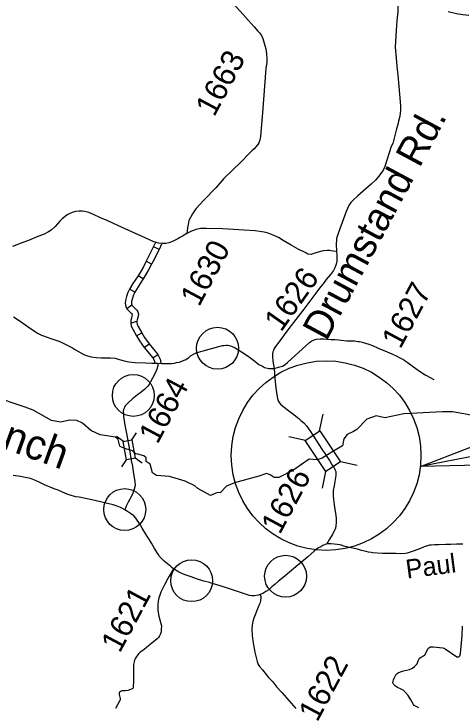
# Model space of a CAD drawing. Extents: x 1376167 to 1379209, y 761324 to 763997.
# Drawn here: x 1376443.7 to 1376526.6, y 762704.2 to 762832.7 of the extents above; entities that cross this region are included whole.
import ezdxf

# ---------------------------------------------------------------- set-up
doc = ezdxf.new("R2010")
doc.units = 0
for name, color, linetype in [('Default', 7, 'Continuous'), ('Old_Level_1', 7, 'Continuous'), ('Prop DSN Text', 7, 'Continuous')]:
    doc.layers.add(name, color=color, linetype=linetype)

msp = doc.modelspace()

# ---------------------------------------------------------------- linework, layer by layer
at = {"layer": 'Default'}
for p, q in [((1376469.55, 762789.54), (1376470.58, 762789.09)), ((1376469.16, 762786.31), (1376468.16, 762786.83)), ((1376467.61, 762783.56), (1376466.65, 762784.15)), ((1376466.05, 762781.14), (1376465.07, 762781.69)), ((1376465.51, 762778.68), (1376464.56, 762778.04)), ((1376465.31, 762775.34), (1376466.43, 762775.71)), ((1376466.35, 762773.02), (1376467.33, 762773.57)), ((1376467.8, 762770.85), (1376468.69, 762771.54)), ((1376469.38, 762768.95), (1376470.33, 762769.57)), ((1376582.4, 762761.32), (1376518.9, 762748.79)), ((1376500.26, 762755.39), (1376500.89, 762758.49)), ((1376463.93, 762753.47), (1376462.64, 762754.37)), ((1376465.49, 762753.75), (1376466.39, 762755.04)), ((1376497.63, 762753.65), (1376494.53, 762754.29)), ((1376463.63, 762748.77), (1376464.53, 762750.07)), ((1376467.41, 762749.45), (1376466.12, 762750.35)), ((1376507.21, 762749.02), (1376504.12, 762749.65)), ((1376500.79, 762744.78), (1376501.42, 762747.87))]:
    msp.add_line(p, q, dxfattribs=at)
for points in [[(1376514.5, 762837.69), (1376514.66, 762835.92), (1376514.73, 762833.03), (1376514.55, 762831.4), (1376514.4, 762829.63), (1376514.26, 762826.49), (1376514.63, 762822.34)], [(1376483.67, 762835.3), (1376486.09, 762832.57), (1376487.01, 762831.53), (1376488.15, 762830.27), (1376488.85, 762829.45), (1376489.15, 762829.14), (1376489.49, 762828.68), (1376489.74, 762828.14), (1376490.13, 762826.84), (1376490.29, 762826.21), (1376490.43, 762825.25), (1376490.51, 762824.42), (1376490.47, 762823.69), (1376490.37, 762823), (1376490.32, 762822.58), (1376489.66, 762814.31), (1376489.29, 762810.01), (1376489.19, 762809.29), (1376489.01, 762808.81), (1376488.83, 762808.48), (1376488.12, 762807.68), (1376487.73, 762807.31), (1376487.42, 762806.98), (1376485.67, 762805.22), (1376482.51, 762802.18), (1376481.04, 762800.47), (1376478.82, 762798.18), (1376477.37, 762796.57), (1376476.71, 762795.62), (1376476.07, 762794.41), (1376475.9, 762793.63), (1376475.79, 762793.04), (1376475.67, 762791.98)], [(1376524.07, 762833.11), (1376525.61, 762832.77), (1376526.77, 762832.56), (1376527.9, 762832.44)], [(1376514.63, 762822.34), (1376514.75, 762821.36), (1376515.22, 762815.63), (1376515.22, 762814.91), (1376515.16, 762814.18), (1376515.05, 762813.46), (1376514.87, 762812.82), (1376514.72, 762812.17), (1376514.47, 762811.36), (1376513.78, 762808.67), (1376513.51, 762808.07), (1376512.33, 762804.41), (1376512.06, 762803.82), (1376511.76, 762803.34), (1376511.14, 762802.52), (1376510.58, 762801.89), (1376509.77, 762801.1), (1376507.33, 762798.95), (1376506.38, 762798.12), (1376506.03, 762797.73), (1376505.66, 762797.19), (1376505.15, 762796.07), (1376504.67, 762794.72), (1376503.73, 762792.18), (1376503.41, 762791.07), (1376503.35, 762790.8), (1376503.3, 762790.03), (1376503.39, 762788.66)], [(1376470.44, 762790.22), (1376469.59, 762790.46), (1376467.3, 762791.5), (1376466.29, 762791.93), (1376462.88, 762793.47), (1376461.08, 762794.3), (1376459.68, 762794.88), (1376458.39, 762795.5), (1376457.53, 762795.85), (1376456.82, 762796.04), (1376456.29, 762796.13), (1376455.77, 762796.11), (1376455.04, 762796.06), (1376454.47, 762795.86), (1376453.91, 762795.62), (1376453.51, 762795.42), (1376453.13, 762795.13), (1376452.63, 762794.71), (1376452.14, 762794.24), (1376451.73, 762793.77), (1376451.3, 762793.28), (1376450.56, 762792.61), (1376450.08, 762792.3), (1376449.39, 762791.92), (1376448.99, 762791.76), (1376448.09, 762791.4), (1376447.25, 762791.05), (1376446.39, 762790.68), (1376445.31, 762790.3), (1376443.4, 762789.59)], [(1376503.39, 762788.66), (1376502.78, 762788.71), (1376502.07, 762788.85), (1376501.63, 762788.85), (1376500.92, 762788.79), (1376499.72, 762788.49), (1376499.02, 762788.2), (1376498.63, 762788.1), (1376498.09, 762788.15), (1376497.7, 762788.39), (1376496.31, 762789.08), (1376495, 762789.84), (1376493.48, 762790.7), (1376492.64, 762791.21), (1376491.63, 762791.7), (1376490.72, 762792.03), (1376490.01, 762792.2), (1376488.34, 762792.45), (1376486.27, 762792.61), (1376482.33, 762792.82), (1376479.3, 762792.93), (1376478.2, 762792.88), (1376477.4, 762792.75), (1376476.56, 762792.41), (1376475.67, 762791.98)], [(1376475.67, 762791.98), (1376474.86, 762791.47), (1376474.37, 762791.24), (1376474.14, 762791.07), (1376473.4, 762790.67), (1376472.69, 762790.35), (1376472.33, 762790.24), (1376471.82, 762790.14), (1376471.13, 762790.11), (1376470.44, 762790.22)], [(1376469.92, 762790.42), (1376469.78, 762790.05), (1376468.61, 762787.7), (1376468.16, 762786.83), (1376467.63, 762785.8), (1376467.21, 762785.08), (1376466.65, 762784.15), (1376466.12, 762783.35), (1376465.7, 762782.7), (1376465.07, 762781.69), (1376464.74, 762781.03), (1376464.5, 762780.32), (1376464.33, 762779.58), (1376464.28, 762779.06), (1376464.33, 762778.74), (1376464.39, 762778.46), (1376464.56, 762778.04), (1376465.4, 762777.23), (1376465.53, 762777.09), (1376465.57, 762777.01), (1376465.58, 762776.99), (1376465.56, 762776.9), (1376465.52, 762776.66), (1376465.42, 762776.32), (1376465.3, 762775.84), (1376465.31, 762775.34), (1376465.4, 762774.81), (1376465.67, 762774.26), (1376466.35, 762773.02), (1376466.91, 762772.08), (1376467.8, 762770.85), (1376469.38, 762768.95), (1376469.68, 762768.36), (1376469.77, 762767.83)], [(1376470.97, 762790.02), (1376470.81, 762789.6), (1376469.62, 762787.19), (1376469.16, 762786.31), (1376468.61, 762785.25), (1376468.18, 762784.51), (1376467.61, 762783.56), (1376467.06, 762782.73), (1376466.65, 762782.1), (1376466.05, 762781.14), (1376465.78, 762780.59), (1376465.59, 762780.02), (1376465.45, 762779.4), (1376465.42, 762779.08), (1376465.44, 762778.92), (1376465.47, 762778.79), (1376465.51, 762778.68), (1376466.2, 762778.02), (1376466.45, 762777.75), (1376466.62, 762777.45), (1376466.74, 762777.05), (1376466.67, 762776.71), (1376466.62, 762776.41), (1376466.5, 762776.01), (1376466.43, 762775.71), (1376466.43, 762775.46), (1376466.49, 762775.16), (1376466.67, 762774.78), (1376467.33, 762773.57), (1376467.85, 762772.7), (1376468.69, 762771.54), (1376470.33, 762769.57), (1376470.76, 762768.72), (1376470.88, 762768.03)], [(1376503.39, 762788.66), (1376503.46, 762788.05), (1376503.46, 762787.48), (1376503.44, 762786.86), (1376503.33, 762786.27), (1376503.07, 762785.64), (1376502.8, 762785.13), (1376502.27, 762784.38), (1376501.46, 762783.47), (1376501.1, 762782.89), (1376500.26, 762781.86), (1376499.55, 762780.95), (1376497.12, 762777.72), (1376495.44, 762775.51), (1376495.01, 762774.96), (1376494.21, 762773.89), (1376492.89, 762772.09), (1376492.11, 762771.07), (1376491.85, 762770.66), (1376491.69, 762770.33), (1376491.61, 762770.07), (1376491.53, 762769.76), (1376491.52, 762769.22), (1376491.61, 762768.32), (1376491.7, 762767.62), (1376491.84, 762766.97)], [(1376443.62, 762776.57), (1376444.84, 762775.72), (1376446.34, 762774.71), (1376447.64, 762773.74), (1376448.04, 762773.53), (1376448.4, 762773.32), (1376448.76, 762773.14), (1376449.99, 762772.69), (1376450.33, 762772.57), (1376451.09, 762772.36), (1376451.83, 762772.1), (1376452.3, 762771.93), (1376452.67, 762771.74), (1376453.02, 762771.54), (1376454.5, 762770.79), (1376455.1, 762770.4), (1376456.05, 762769.88), (1376456.63, 762769.56), (1376457.28, 762769.32), (1376458, 762769.11), (1376458.87, 762768.98), (1376459.82, 762768.92), (1376461.02, 762768.95), (1376461.56, 762768.94), (1376462.39, 762768.86), (1376462.96, 762768.69), (1376463.42, 762768.56), (1376464.09, 762768.39), (1376464.93, 762768.2), (1376466.13, 762768.07), (1376468.09, 762768.02), (1376469.22, 762767.96), (1376469.79, 762767.94), (1376470.32, 762767.93)], [(1376491.84, 762766.97), (1376492.65, 762767.19), (1376493.36, 762767.43), (1376493.9, 762767.71), (1376494.32, 762768.06), (1376498.44, 762771.86), (1376498.83, 762772.12), (1376499.24, 762772.29), (1376499.7, 762772.4), (1376500.35, 762772.45), (1376501.02, 762772.44), (1376501.62, 762772.42), (1376502.42, 762772.37), (1376503.07, 762772.32), (1376503.72, 762772.25), (1376505.21, 762772.12), (1376506.18, 762772.1), (1376506.7, 762772.07), (1376507.31, 762772), (1376507.66, 762771.97), (1376508.14, 762771.84), (1376509.38, 762771.46), (1376510.04, 762771.2), (1376511.11, 762770.71), (1376512.73, 762770.04), (1376513.61, 762769.67), (1376514.44, 762769.3), (1376515.36, 762768.83), (1376515.77, 762768.62), (1376516.11, 762768.39), (1376516.43, 762768.17), (1376517.41, 762767.46), (1376518.32, 762766.81), (1376519.28, 762766.12), (1376519.93, 762765.74), (1376521.39, 762764.92)], [(1376470.32, 762767.93), (1376471.06, 762767.92), (1376471.51, 762767.88), (1376472.15, 762767.9), (1376472.43, 762767.92), (1376472.86, 762767.92), (1376473.4, 762767.98), (1376473.76, 762768.06), (1376474.23, 762768.17), (1376475.34, 762768.6), (1376475.96, 762768.96), (1376476.35, 762769.32), (1376477.06, 762769.7), (1376477.4, 762769.87), (1376478.7, 762770.26), (1376479.8, 762770.56), (1376482.27, 762771.23), (1376482.51, 762771.26), (1376482.98, 762771.29), (1376483.19, 762771.28), (1376483.49, 762771.25), (1376483.96, 762771.1), (1376484.64, 762770.77), (1376486.46, 762769.62), (1376487.3, 762769.07), (1376488.25, 762768.35), (1376489.03, 762767.74), (1376489.66, 762767.38), (1376490.05, 762767.17), (1376490.6, 762767.02), (1376490.87, 762766.95), (1376491.36, 762766.94), (1376491.59, 762766.95), (1376491.84, 762766.97)], [(1376470.32, 762767.93), (1376470.32, 762767.47), (1376470.11, 762766.85), (1376469.74, 762766.01), (1376469.3, 762765.16), (1376468.94, 762764.47), (1376468.68, 762764.03), (1376468.44, 762763.67), (1376467.9, 762763.16), (1376467.25, 762762.6), (1376466.55, 762762.07), (1376465.64, 762761.32), (1376464.89, 762760.69), (1376464.63, 762760.45), (1376464.27, 762760.05), (1376464.12, 762759.77), (1376463.97, 762759.35), (1376463.92, 762759.06), (1376463.93, 762758.55), (1376463.95, 762758.04), (1376464.08, 762757.36), (1376464.2, 762756.46), (1376464.57, 762754.62), (1376464.81, 762753.28), (1376465.04, 762751.93)], [(1376491.84, 762766.97), (1376491.98, 762765.09), (1376492.18, 762763.38), (1376492.31, 762762.07), (1376492.46, 762761.39), (1376492.6, 762760.96), (1376492.74, 762760.66), (1376493, 762760.36), (1376493.47, 762759.97)], [(1376502.68, 762751.6), (1376500.73, 762750.37), (1376499.78, 762750.04), (1376498.32, 762750.14), (1376495.47, 762748.2), (1376492.72, 762746.76), (1376491.87, 762746.76), (1376491.12, 762747.29), (1376490.44, 762747.49), (1376489.02, 762747.02), (1376484.5, 762745.78), (1376483.04, 762745.19), (1376481.85, 762743.93), (1376481.37, 762744), (1376480.07, 762743.47), (1376477.71, 762744.73), (1376477.13, 762745.25), (1376475.36, 762746.12), (1376472.49, 762746.93), (1376470.07, 762747.16), (1376469.3, 762747.66), (1376468.89, 762749.22), (1376468.16, 762749.73), (1376468.13, 762750.42), (1376467.74, 762750.8), (1376466.62, 762751.08), (1376466.26, 762751.15), (1376465.64, 762751.74), (1376464.41, 762752.11), (1376463.73, 762752.31), (1376463.25, 762752.6), (1376462.95, 762753.84), (1376462.45, 762754.25), (1376459.63, 762754.71), (1376457.93, 762755.46), (1376456.38, 762756.87), (1376455.31, 762757.34), (1376454.03, 762757.4), (1376452.28, 762757.05), (1376450.64, 762757.31), (1376447.23, 762759.22), (1376445.76, 762759.78), (1376439.49, 762761.92)], [(1376493.47, 762759.97), (1376494.51, 762759.17), (1376495.21, 762758.65), (1376496.42, 762757.69), (1376496.8, 762757.35), (1376497.34, 762756.88), (1376497.81, 762756.34), (1376498.54, 762755.31), (1376498.88, 762754.8), (1376499.53, 762753.74), (1376500.23, 762752.72), (1376500.57, 762752.21), (1376501.46, 762750.83)], [(1376535.83, 762753.56), (1376534.84, 762755.58), (1376534.52, 762755.95), (1376533.75, 762756.69), (1376532.25, 762757.18), (1376531.28, 762757.6), (1376527.61, 762758.42), (1376524.88, 762758.91), (1376522.97, 762758.97), (1376515.83, 762758.59), (1376512.32, 762757.81), (1376510.71, 762758.22), (1376509.01, 762757.58), (1376507.14, 762755.67), (1376506.54, 762755.28), (1376505.35, 762754.75), (1376504.71, 762753.93), (1376504.47, 762752.63), (1376502.68, 762751.6)], [(1376465.04, 762751.93), (1376465.4, 762749.92), (1376465.59, 762748.88), (1376465.75, 762747.85), (1376466.03, 762746.01), (1376466.1, 762745.3), (1376465.95, 762744.64), (1376465.62, 762743.68), (1376465.27, 762743.01), (1376465.12, 762742.79), (1376464.83, 762742.18), (1376464.46, 762741.44), (1376464.2, 762740.76)], [(1376501.46, 762750.83), (1376502.08, 762749.9), (1376502.57, 762749.07), (1376502.9, 762748.68), (1376503.15, 762748.15), (1376503.23, 762747.89), (1376503.26, 762747.48), (1376503.26, 762747.16), (1376503.09, 762746.03), (1376502.95, 762745.25), (1376502.78, 762744.38), (1376502.79, 762743.4), (1376502.84, 762742.69), (1376502.97, 762741.72), (1376503.05, 762740.87), (1376503.19, 762740.14)], [(1376464.2, 762740.76), (1376463.76, 762741.01), (1376463.41, 762741.19), (1376462.79, 762741.47), (1376462.03, 762741.69), (1376460.98, 762741.94), (1376459.7, 762742.26), (1376458.1, 762742.65), (1376456.94, 762742.86), (1376455.74, 762743.1), (1376455.16, 762743.19), (1376454.26, 762743.43), (1376453.55, 762743.66), (1376452.69, 762744.07), (1376451.88, 762744.4), (1376451.12, 762744.65), (1376449.36, 762745.4), (1376448.48, 762745.82), (1376447.65, 762746.22), (1376446.77, 762746.59), (1376445.78, 762746.78), (1376444.89, 762746.96), (1376443.56, 762747.14)], [(1376473.22, 762729.85), (1376472.97, 762730.06), (1376472.69, 762730.29), (1376471.48, 762731.27), (1376470.63, 762732.14), (1376470.36, 762732.55), (1376469.7, 762733.65), (1376469.4, 762734.16), (1376469.12, 762734.63), (1376468.75, 762735.25), (1376468.4, 762735.77), (1376468.09, 762736.28), (1376467.44, 762737.36), (1376467.05, 762738.06), (1376466.24, 762739.23), (1376465.85, 762739.65), (1376465.23, 762740.08), (1376464.71, 762740.46), (1376464.2, 762740.76)], [(1376503.19, 762740.14), (1376503.29, 762739.23), (1376503.31, 762738.44), (1376503.24, 762737.79), (1376503.17, 762737.41), (1376503.05, 762737.09), (1376502.94, 762736.83), (1376502.59, 762736.16), (1376502.08, 762735.34), (1376501.56, 762734.49)], [(1376501.56, 762734.49), (1376501.18, 762734.29), (1376500.87, 762734.15), (1376500.49, 762733.95), (1376500.06, 762733.72), (1376499.7, 762733.48), (1376499.26, 762733.13), (1376498.05, 762732.09), (1376497.3, 762731.42), (1376495.84, 762730.24), (1376494.32, 762728.93), (1376493.84, 762728.5), (1376492.64, 762727.59), (1376492, 762727.04), (1376491.44, 762726.54), (1376490.84, 762725.99), (1376490.32, 762725.63), (1376489.75, 762725.29), (1376489.25, 762725.07)], [(1376526.78, 762734.42), (1376525.58, 762734.41), (1376524.55, 762734.39), (1376523.6, 762734.36), (1376522.32, 762734.32), (1376521.51, 762734.28), (1376520.93, 762734.25), (1376520.6, 762734.23), (1376519.63, 762733.9), (1376518.9, 762733.61), (1376517.76, 762733.19), (1376516.46, 762732.78), (1376516.13, 762732.7), (1376515.28, 762732.66), (1376514.39, 762732.67), (1376513.02, 762732.67), (1376511.83, 762732.7), (1376510.02, 762732.83), (1376509.78, 762732.87), (1376509.31, 762732.96), (1376508.87, 762733.07), (1376507.98, 762733.27), (1376507.27, 762733.48), (1376505.78, 762733.83), (1376504.92, 762734.02), (1376504.05, 762734.27), (1376503.5, 762734.34), (1376502.4, 762734.46), (1376501.56, 762734.49)], [(1376473.22, 762729.85), (1376472.43, 762728.52), (1376472.16, 762728.06), (1376471.55, 762726.88), (1376470.89, 762725.54), (1376470.73, 762725.18), (1376470.51, 762724.51), (1376470.38, 762723.86), (1376470.3, 762723.22), (1376470.31, 762722.6), (1376470.34, 762722.18), (1376470.37, 762721.78), (1376470.5, 762721.11), (1376470.7, 762720.42), (1376470.87, 762719.74), (1376470.96, 762719.28), (1376470.95, 762718.69), (1376470.91, 762718.16), (1376470.82, 762717.84), (1376470.62, 762717.41), (1376470.42, 762717.13), (1376470.17, 762716.89), (1376469.5, 762716.34), (1376468.57, 762715.56), (1376468.18, 762715.21), (1376467.51, 762714.74), (1376467.05, 762714.44), (1376466.78, 762714.18), (1376466.35, 762713.61), (1376466.18, 762713.33), (1376466.01, 762712.93), (1376465.91, 762712.62), (1376465.82, 762712.1), (1376465.81, 762711.48), (1376465.82, 762710.46), (1376465.83, 762709.05), (1376465.76, 762707.99), (1376465.75, 762707.78), (1376465.69, 762707.67), (1376465.53, 762707.59), (1376465.26, 762707.49), (1376464.78, 762707.34), (1376464.27, 762707.26), (1376463.66, 762707.22), (1376463.51, 762707.18), (1376463.34, 762707.08), (1376463.22, 762707.02), (1376463.16, 762706.88), (1376463.16, 762706.6), (1376463.19, 762706.34), (1376463.35, 762705.84), (1376463.32, 762705.6), (1376463.21, 762705.33), (1376462.89, 762704.78), (1376462.45, 762703.97)], [(1376489.25, 762725.07), (1376488.88, 762724.99), (1376488.22, 762724.85), (1376487.69, 762724.84), (1376487.26, 762724.93), (1376486.73, 762725.1), (1376486, 762725.33), (1376485.24, 762725.58), (1376483.18, 762726.28), (1376481.82, 762726.7), (1376480.62, 762727.07), (1376480.16, 762727.2), (1376479.87, 762727.3), (1376478.84, 762727.56), (1376477.47, 762728.01), (1376476.51, 762728.34), (1376475.73, 762728.59), (1376474.9, 762728.93), (1376474.03, 762729.37), (1376473.22, 762729.85)], [(1376489.25, 762725.07), (1376489.4, 762724.75), (1376489.39, 762724.46), (1376489.3, 762723.9), (1376489.17, 762723.46), (1376489.01, 762723.04), (1376488.08, 762720.72), (1376487.88, 762720.12), (1376487.76, 762719.42), (1376487.7, 762718.62), (1376487.75, 762717.5), (1376487.87, 762716.52), (1376488.08, 762715.43), (1376488.25, 762714.44), (1376488.45, 762713.67), (1376488.68, 762712.68), (1376488.89, 762712.15), (1376489.1, 762711.78), (1376489.67, 762711.12), (1376490.34, 762710.3), (1376490.82, 762709.74), (1376491.57, 762708.89), (1376492.34, 762707.91), (1376493.25, 762706.92), (1376495.87, 762703.95)], [(1376518.63, 762704.09), (1376517.78, 762704.54), (1376517.62, 762704.74), (1376517.13, 762705.61), (1376516.64, 762706.39), (1376516.17, 762706.95), (1376515.93, 762707.18), (1376515.85, 762707.3), (1376515.25, 762707.59), (1376514.7, 762707.87), (1376514.49, 762707.99), (1376514.32, 762708.13), (1376513.96, 762708.47), (1376513.83, 762708.74), (1376513.84, 762709.02), (1376513.96, 762709.28), (1376514.12, 762709.72), (1376514.38, 762710.21), (1376514.61, 762710.43), (1376514.82, 762710.58), (1376515.24, 762710.76), (1376515.79, 762710.96), (1376516.33, 762711.08), (1376516.87, 762711.21), (1376517.43, 762711.43), (1376517.83, 762711.74), (1376518.13, 762712.07), (1376518.32, 762712.28), (1376518.52, 762712.79), (1376518.59, 762713.03), (1376518.76, 762713.32), (1376519.05, 762713.48), (1376519.5, 762713.71), (1376519.73, 762713.89), (1376520.03, 762714.48), (1376520.29, 762715.01), (1376520.49, 762715.22), (1376520.8, 762715.39), (1376521.3, 762715.4), (1376523.06, 762715.21), (1376523.28, 762715.14), (1376523.5, 762715.03), (1376525.64, 762713.54), (1376525.87, 762713.52), (1376526.05, 762713.55), (1376526.22, 762713.76), (1376526.33, 762714.11), (1376526.41, 762714.84), (1376526.54, 762716.16), (1376526.63, 762717.52), (1376526.69, 762719.23)]]:
    msp.add_lwpolyline(points, dxfattribs=at)
for points in [[(1376538.01, 762749.25), (1376518.9, 762748.79), (1376536.83, 762755.74), (1376535.12, 762751.99)], [(1376501.42, 762747.87), (1376497.61, 762753.64), (1376500.31, 762755.43), (1376504.12, 762749.65)], [(1376464.53, 762750.07), (1376463.92, 762753.47), (1376465.51, 762753.75), (1376466.12, 762750.35)]]:
    msp.add_lwpolyline(points, close=True, dxfattribs=at)
at = {"layer": 'Old_Level_1'}
msp.add_circle((1376501.46, 762750.83), 17.56, dxfattribs=at)
at = {"layer": 'Prop DSN Text'}
for centre in [(1376481.36, 762770.72), (1376465.77, 762761.97), (1376464.18, 762740.84), (1376476.57, 762727.65), (1376493.96, 762728.49)]:
    msp.add_circle(centre, 3.88, dxfattribs=at)

# ---------------------------------------------------------------- texts
at = {"layer": 'Default'}
msp.add_text('Branch', height=5.58, rotation=340.1164, dxfattribs=at).set_placement((1376430.32, 762756.25))
at = {"layer": 'Old_Level_1'}
for s, height, rotation, p in [('1663', 4.185, 61.8015, (1376480.74, 762813.45)), ('Drumstand Rd.', 5.275, 61.8015, (1376501.51, 762771.87)), ('1630', 4.185, 61.8015, (1376477.94, 762778.26)), ('1626', 4.185, 54.7526, (1376493.13, 762773.58)), ('1627', 4.185, 61.8015, (1376515.2, 762770.43)), ('1664', 4.185, 61.8015, (1376470.24, 762752.79)), ('1626', 4.185, 61.8015, (1376492.89, 762736.06)), ('Paul', 3.488, 7.3766, (1376516.42, 762728.04)), ('1621', 4.185, 61.8015, (1376463.26, 762714.1)), ('1622', 4.185, 61.8015, (1376499.82, 762701.32))]:
    msp.add_text(s, height=height, rotation=rotation, dxfattribs=at).set_placement(p)

doc.saveas('drawing.dxf')
